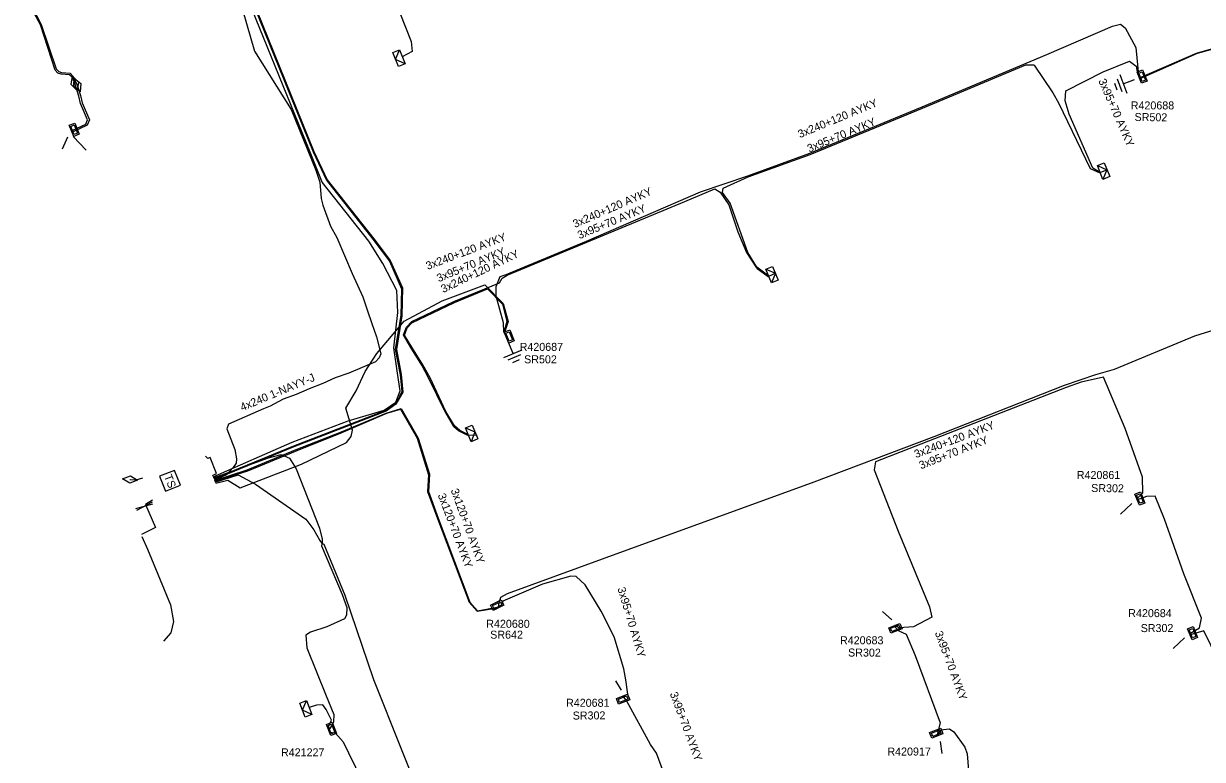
# Model space of a CAD drawing. Extents: x -540028 to -538776, y -1157064 to -1155670.
# Drawn here: x -539965.8 to -539818.5, y -1156336.1 to -1156244.1 of the extents above; entities that cross this region are included whole.
import ezdxf

# ---------------------------------------------------------------- set-up
doc = ezdxf.new("R2010")
doc.units = 0
for name, color, linetype in [('Vrstva 15', 7, 'Continuous'), ('Vrstva 19', 7, 'Continuous'), ('Vrstva 2', 7, 'Continuous'), ('Vrstva 25', 7, 'Continuous'), ('Vrstva 28', 7, 'Continuous'), ('Vrstva 29', 7, 'Continuous'), ('Vrstva 30', 7, 'Continuous'), ('Vrstva 31', 7, 'Continuous'), ('Vrstva 5', 7, 'Continuous'), ('Vrstva 52', 7, 'Continuous'), ('Vrstva 59', 7, 'Continuous'), ('Vrstva 6', 7, 'Continuous'), ('Vrstva 9', 7, 'Continuous')]:
    doc.layers.add(name, color=color, linetype=linetype)

# ---------------------------------------------------------------- blocks, each defined once
blk = doc.blocks.new('17')
at = {"layer": 'Vrstva 2'}
blk.add_lwpolyline([(-1.875, 0), (0, 0.9375), (1.875, 0), (0, -0.9375)], close=True, dxfattribs=at)
blk = doc.blocks.new('30')
at = {"layer": 'Vrstva 2'}
blk.add_lwpolyline([(-2, 0), (2, 0), (2, 4), (-2, 4)], close=True, dxfattribs=at)
blk.add_text('TS', height=2, dxfattribs=at).set_placement((-1.598, 1))
blk = doc.blocks.new('132')
at = {"layer": 'Vrstva 2'}
for points in [[(-1.5, 1.5), (1.5, 1.5), (1.5, 0), (-1.5, 0)], [(-1.1, 1.2), (1.1, 1.2), (1.1, 0.3), (-1.1, 0.3)]]:
    blk.add_lwpolyline(points, close=True, dxfattribs=at)
blk = doc.blocks.new('23')
at = {"layer": 'Vrstva 2'}
blk.add_lwpolyline([(1.875, -1.8), (-1.875, -1.8), (-1.875, 0), (1.875, 0)], close=True, dxfattribs=at)
blk.add_lwpolyline([(1.875, 0), (0, -1.8), (-1.875, 0)], dxfattribs=at)
blk = doc.blocks.new('11')
at = {"layer": 'Vrstva 2'}
for p, q in [((0, -4.3), (0, -1.3)), ((-2.5, -4.3), (2.5, -4.3)), ((-1.7, -5.3), (1.7, -5.3)), ((-0.9, -6.3), (0.9, -6.3))]:
    blk.add_line(p, q, dxfattribs=at)

msp = doc.modelspace()

# ---------------------------------------------------------------- linework, layer by layer
at = {"layer": 'Vrstva 5'}
for points in [[(-539929.85, -1156224.17), (-539930.45, -1156223.35), (-539931.74, -1156223.48), (-539940.8, -1156227.24), (-539942, -1156228.53), (-539941.76, -1156230.14), (-539929.6, -1156260.15), (-539927.94, -1156263.7), (-539922.13, -1156271.08), (-539920.05, -1156273.79), (-539918.56, -1156277.25), (-539918.64, -1156280.6), (-539919.35, -1156284.8), (-539918.71, -1156288.03), (-539918.53, -1156290.1), (-539919.21, -1156291.58), (-539920.51, -1156292.49), (-539932.04, -1156296.91), (-539942.01, -1156300.99)], [(-539929.97, -1156224.22), (-539930.51, -1156223.48), (-539931.71, -1156223.6), (-539940.73, -1156227.34), (-539941.88, -1156228.57), (-539941.64, -1156230.11), (-539929.49, -1156260.1), (-539927.84, -1156263.64), (-539922.03, -1156271.01), (-539919.95, -1156273.72), (-539918.44, -1156277.16), (-539918.51, -1156280.66), (-539919.17, -1156284.83), (-539918.59, -1156287.98), (-539918.37, -1156290.17), (-539919.25, -1156291.69), (-539920.45, -1156292.57), (-539931.99, -1156297.03), (-539941.96, -1156301.1)], [(-539942.1, -1156300.77), (-539932.23, -1156296.44), (-539925.21, -1156293.77), (-539920.73, -1156292.42), (-539919.27, -1156291.43), (-539918.72, -1156290.03), (-539919.04, -1156287.79), (-539919.52, -1156284.66), (-539919.01, -1156280.21), (-539919.12, -1156277.49), (-539920.89, -1156274.11), (-539922.63, -1156271.3), (-539928.45, -1156263.92), (-539929.95, -1156260.19), (-539942.08, -1156230.36), (-539943.02, -1156227.9), (-539944.17, -1156228.16), (-539948.74, -1156229.59), (-539952.12, -1156230.94), (-539964.96, -1156235.96), (-539965.78, -1156237.17)], [(-539941.38, -1156232.1), (-539936.93, -1156247.59), (-539932.33, -1156254.87), (-539929.25, -1156262.42), (-539928.76, -1156263.96), (-539928.59, -1156265.96), (-539928.39, -1156266.8), (-539927.41, -1156269.42), (-539926.63, -1156270.87), (-539924.73, -1156275.35), (-539924.03, -1156276.81), (-539923.37, -1156278.25), (-539922.84, -1156279.91), (-539922.26, -1156281.6), (-539921.68, -1156283.28), (-539921.14, -1156285.4), (-539921.35, -1156285.89), (-539921.81, -1156286.38), (-539925.13, -1156287.8), (-539926.85, -1156288.4), (-539928.38, -1156289.08), (-539930.09, -1156289.78), (-539931.73, -1156290.47), (-539933.35, -1156291.04), (-539934.97, -1156291.93), (-539935.78, -1156292.28), (-539940.17, -1156294.16), (-539940.37, -1156294.75), (-539939.38, -1156297.33), (-539939.15, -1156298.5), (-539939.22, -1156299.04), (-539939.58, -1156299.61), (-539940.43, -1156300.51), (-539941.97, -1156301.23)], [(-539964.81, -1156241.81), (-539964.72, -1156242.06), (-539963.57, -1156244.25), (-539961.69, -1156249.79), (-539961.38, -1156250.13), (-539961.04, -1156250.23), (-539959.94, -1156250.32), (-539959.56, -1156250.72), (-539959.07, -1156251.81)], [(-539959.37, -1156251.58), (-539959.72, -1156250.84), (-539960.04, -1156250.52), (-539961.08, -1156250.43), (-539961.48, -1156250.31), (-539961.83, -1156249.93), (-539963.68, -1156244.3), (-539964.69, -1156242.37)], [(-539905.77, -1156282.67), (-539905.81, -1156281.52), (-539906.74, -1156278.18), (-539906.73, -1156276.96), (-539906.22, -1156275.71), (-539905.46, -1156275.47), (-539895.43, -1156271.31), (-539881.19, -1156265.13), (-539875.26, -1156263.16), (-539867.55, -1156260.33), (-539853.49, -1156254.51), (-539837.92, -1156248), (-539829.69, -1156244.45), (-539828.72, -1156244.19), (-539828.11, -1156244.65), (-539826.81, -1156247.11), (-539826.46, -1156250.57)], [(-539826.32, -1156250.92), (-539819.2, -1156247.81), (-539815.3, -1156246.71), (-539812.7, -1156246.18), (-539811.25, -1156246.22), (-539810.27, -1156247.55), (-539806.46, -1156257.83), (-539802.57, -1156267.21), (-539802.46, -1156267.55), (-539802.39, -1156269.2), (-539802.99, -1156270.08), (-539808.42, -1156272.37), (-539815.96, -1156276.02), (-539816.4, -1156276.72), (-539816.57, -1156277.55), (-539814.42, -1156282.68), (-539813.56, -1156284.02), (-539812.88, -1156284.3), (-539809.79, -1156283.14), (-539808.99, -1156283.54), (-539808.71, -1156284.18), (-539808.23, -1156285.27)], [(-539808.35, -1156285.31), (-539808.75, -1156284.2), (-539809.01, -1156283.6), (-539809.72, -1156283.25), (-539812.86, -1156284.41), (-539813.59, -1156284.05), (-539814.52, -1156282.66), (-539816.7, -1156277.62), (-539816.54, -1156276.68), (-539816.05, -1156275.98), (-539808.42, -1156272.29), (-539803.07, -1156269.92), (-539802.5, -1156269.11), (-539802.7, -1156267.67), (-539802.75, -1156267.34), (-539806.55, -1156257.87), (-539810.37, -1156247.64), (-539811.34, -1156246.27), (-539812.66, -1156246.28), (-539815.33, -1156246.82), (-539819.13, -1156247.88), (-539826.28, -1156251.03)], [(-539910.2, -1156295.5), (-539910.28, -1156295.59), (-539911.41, -1156295), (-539912, -1156294.5), (-539913.13, -1156292.56), (-539915.13, -1156288.46), (-539916.03, -1156286.81), (-539917.38, -1156284.6), (-539918.3, -1156283.02), (-539917.94, -1156282.04), (-539917.25, -1156281.36), (-539912, -1156278.86), (-539906.32, -1156276.5), (-539905.97, -1156275.92), (-539905.34, -1156275.56), (-539895.41, -1156271.44), (-539883.13, -1156266.35), (-539879.42, -1156264.76), (-539878.72, -1156265.19), (-539877.65, -1156266.78), (-539876.54, -1156270.14), (-539875.46, -1156272.74), (-539874.18, -1156274.63), (-539874.1, -1156274.71), (-539872.72, -1156275.74), (-539872.67, -1156275.67), (-539874.15, -1156274.57), (-539875.29, -1156272.71), (-539877.5, -1156266.58), (-539878.44, -1156265.25), (-539878.37, -1156264.68), (-539875.23, -1156263.26), (-539867.47, -1156260.49), (-539853.46, -1156254.68), (-539840.56, -1156249.29), (-539839.59, -1156249.26), (-539839.48, -1156249.31), (-539837.15, -1156252.76), (-539836.44, -1156254.04), (-539832.49, -1156262.23), (-539831.28, -1156262.79), (-539831.25, -1156262.72), (-539832.18, -1156262.19), (-539835.12, -1156255.46), (-539835.63, -1156253.78), (-539835.53, -1156252.52), (-539830.88, -1156250.14), (-539827.6, -1156248.83), (-539826.74, -1156249.43), (-539826.63, -1156250.16)], [(-539959.7, -1156257.48), (-539957.99, -1156256.68), (-539957.77, -1156256.16), (-539958.66, -1156254.09), (-539958.86, -1156253.18), (-539959.37, -1156251.58)], [(-539959.07, -1156251.81), (-539958.66, -1156253.12), (-539958.46, -1156254.03), (-539957.55, -1156256.16), (-539957.84, -1156256.83), (-539959.66, -1156257.68)], [(-539941.77, -1156301.55), (-539940.27, -1156301.18), (-539938.72, -1156302.15), (-539931.05, -1156299.18), (-539925.42, -1156296.46), (-539924.83, -1156295.73), (-539924.68, -1156294.92), (-539925.5, -1156292.19), (-539924.22, -1156290.02), (-539923.08, -1156287.58), (-539921.64, -1156285.34), (-539918.2, -1156281.3), (-539913.47, -1156278.77), (-539908.13, -1156276.75), (-539905.84, -1156279.11), (-539905.24, -1156281.35), (-539905.67, -1156282.74)], [(-539910.2, -1156295.5), (-539911.27, -1156294.98), (-539911.91, -1156294.39), (-539913.02, -1156292.58), (-539914.98, -1156288.4), (-539915.87, -1156286.75), (-539917.27, -1156284.55), (-539918.19, -1156283.05), (-539917.83, -1156282.16), (-539917.26, -1156281.5), (-539911.95, -1156278.97), (-539907.82, -1156277.25), (-539905.95, -1156279.17), (-539905.37, -1156281.35), (-539905.78, -1156282.67)], [(-539808.1, -1156285.22), (-539809.67, -1156280.95), (-539810.49, -1156280.4), (-539819.47, -1156283.18), (-539829.52, -1156287.35), (-539831.83, -1156288.01), (-539835.74, -1156289.34), (-539852.03, -1156295.75), (-539867.05, -1156301.42), (-539893.47, -1156311.06), (-539905.35, -1156315.36), (-539906.2, -1156315.83), (-539906.45, -1156316.73), (-539906.39, -1156317.1)], [(-539826.65, -1156303.5), (-539825.91, -1156302.74), (-539825.95, -1156300.82), (-539828.11, -1156294.73), (-539830.84, -1156288.3), (-539833.64, -1156288.94), (-539835.52, -1156289.61), (-539859.32, -1156298.88), (-539859.49, -1156299.89), (-539856.51, -1156307.54), (-539852.59, -1156317), (-539852.3, -1156318.28), (-539854.58, -1156319.5), (-539856.37, -1156319.62), (-539856.89, -1156319.33)], [(-539941.91, -1156301.22), (-539937.83, -1156299.9), (-539931.71, -1156297.34), (-539926.07, -1156295.14), (-539920.48, -1156292.79), (-539918.6, -1156292.21), (-539916.47, -1156295.91), (-539915.05, -1156300.43), (-539915.18, -1156302.6), (-539913.97, -1156305.91), (-539910.02, -1156316.42), (-539909.05, -1156317.49), (-539906.85, -1156317.08), (-539906.56, -1156317.18)], [(-539941.87, -1156301.32), (-539937.77, -1156299.99), (-539931.6, -1156297.48), (-539926.08, -1156295.25), (-539920.38, -1156292.8), (-539918.67, -1156292.3), (-539916.58, -1156295.91), (-539915.16, -1156300.51), (-539915.32, -1156302.61), (-539914.07, -1156305.98), (-539910.11, -1156316.43), (-539909.09, -1156317.53), (-539907.02, -1156317.19), (-539906.7, -1156317.25)], [(-539942.17, -1156300.59), (-539941.66, -1156300.35), (-539942.46, -1156298.34), (-539942.75, -1156298.46)], [(-539942.05, -1156300.88), (-539935.18, -1156298.39), (-539933.57, -1156297.98), (-539932.55, -1156298.43), (-539931.71, -1156299.77), (-539928.78, -1156307.19), (-539928.45, -1156308.54), (-539928.48, -1156308.97), (-539928.55, -1156309.39), (-539925.97, -1156315.45), (-539925.37, -1156317.09), (-539925.41, -1156318.04), (-539925.66, -1156318.51), (-539927.9, -1156319.5), (-539929.94, -1156320.16), (-539930.52, -1156320.56), (-539930.39, -1156322.14), (-539927.97, -1156328.13), (-539927, -1156330.46), (-539927.05, -1156331.36), (-539927.23, -1156331.75), (-539927.51, -1156332.19), (-539927.66, -1156332.32)], [(-539952.48, -1156301.08), (-539952.46, -1156301.09)], [(-539952.46, -1156301.09), (-539951.7, -1156301.15), (-539950.89, -1156300.87)], [(-539941.82, -1156301.44), (-539938.97, -1156300.5), (-539936.79, -1156301.69), (-539930.52, -1156306.05), (-539929.51, -1156307.39), (-539928.75, -1156308.7), (-539928.53, -1156308.99), (-539928.27, -1156309.17), (-539925.64, -1156315.53), (-539922.05, -1156326.09), (-539915.12, -1156343.4), (-539909.49, -1156358.13), (-539908.06, -1156361.94), (-539905.39, -1156369.41), (-539901.58, -1156379.05), (-539900.46, -1156379.61), (-539888.32, -1156374.88), (-539884.55, -1156373.45), (-539883.45, -1156373.33), (-539882.51, -1156373.91), (-539882.12, -1156374.91)], [(-539949.7, -1156303.91), (-539951.67, -1156304.97)], [(-539949.66, -1156303.69), (-539950.54, -1156304.2), (-539949.29, -1156307.1), (-539951.05, -1156307.98)], [(-539820.06, -1156320.35), (-539818.83, -1156319.64), (-539818.59, -1156318.43), (-539820.8, -1156312.87), (-539823.2, -1156306.05), (-539824.38, -1156303.16), (-539825.48, -1156303.21), (-539826.59, -1156303.64)], [(-539951, -1156308.2), (-539950.31, -1156309.79), (-539947.42, -1156316.76), (-539947.04, -1156318.85), (-539947.37, -1156320.26), (-539948.28, -1156321.31)], [(-539786.69, -1156308.23), (-539786.54, -1156308.51), (-539785.86, -1156308.98), (-539783.04, -1156307.79), (-539782.4, -1156307.75), (-539781.84, -1156308.29), (-539779.58, -1156313.15), (-539777.72, -1156317.26), (-539777.6, -1156318.14), (-539778.7, -1156318.77), (-539784.02, -1156320.88), (-539795.1, -1156324.88), (-539804.64, -1156328.28), (-539811.88, -1156330.75), (-539813.44, -1156331.06), (-539814.03, -1156330.55), (-539816.6, -1156323.5), (-539818.29, -1156320), (-539820, -1156320.5)], [(-539890.27, -1156327.93), (-539890.51, -1156326.13), (-539890.79, -1156324.76), (-539891.99, -1156320.75), (-539893.62, -1156317.55), (-539895.61, -1156314.27), (-539896.72, -1156313.2), (-539897.39, -1156313.19), (-539900.93, -1156314.18), (-539905.9, -1156316.29), (-539906.14, -1156316.97)], [(-539857.03, -1156319.39), (-539856.41, -1156319.98), (-539855.48, -1156320.4), (-539854.36, -1156323.09), (-539851.24, -1156331.51), (-539851.66, -1156333.13)], [(-539885.44, -1156341.94), (-539884.76, -1156340.49), (-539886.71, -1156335.29), (-539887.45, -1156334.2), (-539890.38, -1156328.79), (-539890.85, -1156328.17)], [(-539851.54, -1156333.08), (-539851.21, -1156332.39), (-539850.06, -1156332.25), (-539849.52, -1156332.63), (-539848.15, -1156334.54), (-539847.87, -1156335.36), (-539847.39, -1156341.57), (-539846.75, -1156343.97), (-539847.83, -1156345.24), (-539869.95, -1156353.67), (-539873.81, -1156355.44), (-539877.19, -1156356.85), (-539877.66, -1156356.53), (-539878.12, -1156355.68), (-539881.63, -1156346.99), (-539883.21, -1156344.42), (-539884.57, -1156342.46)], [(-539927.53, -1156332.65), (-539926.84, -1156332.76), (-539925.84, -1156333.86), (-539925.16, -1156335.25), (-539922.52, -1156340.69), (-539921.62, -1156343.84), (-539921.58, -1156345.08), (-539921.89, -1156345.51), (-539922.22, -1156345.68)]]:
    msp.add_lwpolyline(points, dxfattribs=at)
at = {"layer": 'Vrstva 52'}
for points in [[(-539929.63, -1156224.08), (-539930.26, -1156222.95), (-539930.08, -1156222.12), (-539928.08, -1156221.32), (-539927.28, -1156221.72), (-539926.29, -1156223.58), (-539923.17, -1156231.59), (-539917.33, -1156246.36), (-539917.23, -1156247.61), (-539918.46, -1156248.28)], [(-539927.75, -1156332.1), (-539927.32, -1156331.15), (-539927.98, -1156329.85), (-539928.4, -1156329.25), (-539929.19, -1156329.27), (-539930.09, -1156329.58)]]:
    msp.add_lwpolyline(points, dxfattribs=at)
at = {"layer": 'Vrstva 59'}
for points in [[(-539960.3, -1156258.31), (-539960.97, -1156259.81)], [(-539959.57, -1156258.25), (-539957.97, -1156259.93)], [(-539831.25, -1156262.72), (-539830.32, -1156262.35)], [(-539872.67, -1156275.67), (-539871.74, -1156275.28)], [(-539910.2, -1156295.5), (-539909.08, -1156295.57)], [(-539942.75, -1156298.46), (-539943.04, -1156298.17)], [(-539827.28, -1156304.09), (-539828.69, -1156305.44)], [(-539857.28, -1156318.61), (-539858.47, -1156317.59)], [(-539820.7, -1156320.87), (-539822.12, -1156322.22)], [(-539891.08, -1156327.42), (-539891.75, -1156326.24)], [(-539851.26, -1156333.81), (-539851.02, -1156335.33)]]:
    msp.add_lwpolyline(points, dxfattribs=at)
at = {"layer": 'Vrstva 9'}
msp.add_lwpolyline([(-539951.73, -1156304.72), (-539949.62, -1156304.15)], dxfattribs=at)

# ---------------------------------------------------------------- block references
at = {"layer": 'Vrstva 15'}
for p, xscale, yscale, rotation in [((-539826.36, -1156250.89), 0.5000000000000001, 0.5000000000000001, -69.54079447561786), ((-539905.44, -1156283.37), 0.5, 0.5, 22.5070472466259)]:
    msp.add_blockref('11', p, dxfattribs=dict(at, xscale=xscale, yscale=yscale, rotation=rotation))
at = {"layer": 'Vrstva 19', "yscale": 0.5}
for p, xscale, rotation in [((-539959.37, -1156251.58), 0.49999999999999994, -72.34248054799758), ((-539959.07, -1156251.81), 0.5, -65.90121938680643), ((-539952.46, -1156301.09), 0.5, -4.5139884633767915)]:
    msp.add_blockref('17', p, dxfattribs=dict(at, xscale=xscale, rotation=rotation))
at = {"layer": 'Vrstva 25', "xscale": 0.5, "yscale": 0.5, "rotation": -68.56623885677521}
msp.add_blockref('30', (-539948.41, -1156301.61), dxfattribs=at)
at = {"layer": 'Vrstva 28'}
for p, xscale, yscale, rotation in [((-539826.36, -1156250.89), 0.5000000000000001, 0.5, -67.91706948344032), ((-539959.79, -1156257.53), 0.5, 0.5, -67.60638894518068), ((-539905.44, -1156283.37), 0.5, 0.5, -67.49402778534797), ((-539826.63, -1156303.61), 0.5, 0.5, -68.56335282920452), ((-539906.43, -1156317.14), 0.49999999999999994, 0.5000000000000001, 25.79490266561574), ((-539856.98, -1156319.34), 0.5, 0.5, -158.6783720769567), ((-539820.05, -1156320.43), 0.5, 0.5, -68.5594278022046), ((-539891, -1156328.2), 0.5000000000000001, 0.5, -158.66936948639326), ((-539927.66, -1156332.4), 0.5, 0.5000000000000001, -68.72039448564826), ((-539851.6, -1156333.13), 0.5, 0.49999999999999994, 21.32804726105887)]:
    msp.add_blockref('132', p, dxfattribs=dict(at, xscale=xscale, yscale=yscale, rotation=rotation))
at = {"layer": 'Vrstva 31', "xscale": 0.5, "yscale": 0.5}
for p, rotation in [((-539918.46, -1156248.28), -68.17661662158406), ((-539831.25, -1156262.72), 112.05031389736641), ((-539872.67, -1156275.67), 112.48755278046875), ((-539910.2, -1156295.5), 112.6256583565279), ((-539930.09, -1156329.58), -68.08591663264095)]:
    msp.add_blockref('23', p, dxfattribs=dict(at, rotation=rotation))

# ---------------------------------------------------------------- texts
at = {"layer": 'Vrstva 29'}
for s, p in [('R420688', (-539827.43, -1156254.85)), ('R420687', (-539903.79, -1156285.02)), ('R420861', (-539834.17, -1156301.03)), ('R420684', (-539827.74, -1156318.29)), ('R420680', (-539907.96, -1156319.62)), ('R420683', (-539863.76, -1156321.68)), ('R420681', (-539897.99, -1156329.49)), ('R421227', (-539933.61, -1156335.68)), ('R420917', (-539857.84, -1156335.58))]:
    msp.add_text(s, height=1, dxfattribs=at).set_placement(p)
at = {"layer": 'Vrstva 30'}
for s, rotation, p in [('SR502', 359.215, (-539826.96, -1156256.29)), ('SR502', 359.943, (-539903.23, -1156286.57)), ('SR302', 359.276, (-539832.38, -1156302.65)), ('SR302', 0.228, (-539826.19, -1156320.16)), ('SR642', 0.073, (-539907.47, -1156320.98)), ('SR302', 359.789, (-539862.75, -1156323.21)), ('SR302', 0.437, (-539897.16, -1156331.09))]:
    msp.add_text(s, height=1, rotation=rotation, dxfattribs=at).set_placement(p)
at = {"layer": 'Vrstva 6'}
for s, rotation, p in [('3x95+70 AYKY', 293.599, (-539831.5, -1156251.27)), ('3x240+120 AYKY', 22.481, (-539868.77, -1156258.45)), ('3x95+70 AYKY', 22.514, (-539867.61, -1156260.25)), ('3x240+120 AYKY', 23.466, (-539896.88, -1156269.67)), ('3x95+70 AYKY', 22.526, (-539896.32, -1156271.07)), ('3x240+120 AYKY', 20.692, (-539915.28, -1156274.91)), ('3x95+70 AYKY', 22.572, (-539913.9, -1156276.45)), ('3x240+120 AYKY', 25.493, (-539913.34, -1156277.8)), ('4x240 1-NAYY-J', 22.818, (-539938.46, -1156292.57)), ('3x240+120 AYKY', 20.683, (-539854.27, -1156298.43)), ('3x95+70 AYKY', 21.285, (-539853.65, -1156299.83)), ('3x120+70 AYKY', 290.757, (-539914.04, -1156303.04)), ('3x120+70 AYKY', 289.968, (-539912.42, -1156302.43)), ('3x95+70 AYKY', 286.676, (-539891.58, -1156314.7)), ('3x95+70 AYKY', 290.386, (-539851.93, -1156320.24)), ('3x95+70 AYKY', 290.496, (-539885.04, -1156327.85))]:
    msp.add_text(s, height=1, rotation=rotation, dxfattribs=at).set_placement(p)

doc.saveas('drawing.dxf')
